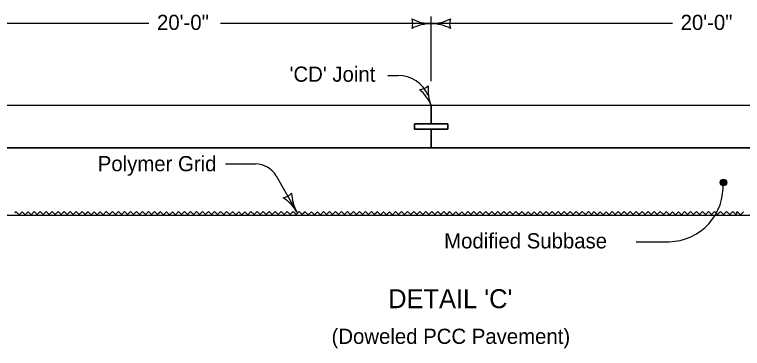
# Model space of a CAD drawing. Extents: x 5546 to 81668, y 3174 to 15999.
# Drawn here: x 14429 to 15194, y 8443 to 8795 of the extents above; entities that cross this region are included whole.
import ezdxf

# ---------------------------------------------------------------- set-up
doc = ezdxf.new("R2010")
doc.units = 0
for name, color, linetype in [('PS_BOLT', 7, 'Continuous'), ('PS_CONST', 7, 'Continuous'), ('PS_DAWA', 7, 'Continuous'), ('PS_SHAPE', 7, 'Continuous')]:
    doc.layers.add(name, color=color, linetype=linetype)

msp = doc.modelspace()

# ---------------------------------------------------------------- linework, layer by layer
at = {"layer": 'PS_BOLT'}
for p, q in [((14866.72, 8699.17), (14310.64, 8699.17)), ((15417.71, 8699.17), (14866.72, 8699.17)), ((14866.72, 8699.17), (14866.72, 8679.74)), ((14866.72, 8679.79), (14866.72, 8699.17)), ((14849.09, 8674.22), (14849.1, 8679.75)), ((14849.1, 8679.75), (14883.63, 8679.75)), ((14883.63, 8679.75), (14866.72, 8679.79)), ((14866.72, 8679.74), (14884.34, 8679.73)), ((14884.34, 8679.73), (14884.34, 8674.16)), ((14866.7, 8674.15), (14849.09, 8674.23)), ((14866.72, 8654.62), (14866.7, 8674.21)), ((14866.73, 8674.16), (14866.72, 8654.62)), ((14884.34, 8674.16), (14866.73, 8674.16)), ((14310.64, 8654.62), (14866.72, 8654.62)), ((14866.72, 8654.62), (15305.81, 8654.62))]:
    msp.add_line(p, q, dxfattribs=at)
at = {"layer": 'PS_CONST'}
for p, q in [((14821.22, 8730.75), (14831.56, 8730.75)), ((14650.52, 8637.6), (14681.92, 8637.6)), ((14703.61, 8625.03), (14725.55, 8586.74)), ((15082.31, 8555.61), (15116.87, 8555.61))]:
    msp.add_line(p, q, dxfattribs=at)
msp.add_lwpolyline([(15173.91, 8614.82), (15175.07, 8615.35), (15176.89, 8615.91), (15177.24, 8617.76), (15177, 8619.38), (15175.83, 8620.87), (15174.1, 8620.72), (15172.27, 8620.47), (15171.4, 8619.01), (15171.24, 8617.48), (15172.31, 8615.47), (15173.64, 8615.31), (15175.47, 8615.77), (15176.96, 8616.93), (15176.91, 8618.66), (15175.75, 8620.06), (15174.12, 8620.21), (15172.29, 8619.86), (15172.01, 8618.83), (15171.65, 8617.59), (15172.5, 8616.09), (15173.83, 8616.13), (15175.35, 8616.37), (15176.44, 8617.22), (15175.89, 8618.74), (15174.75, 8619.62), (15173.21, 8619.68), (15172.83, 8618.85), (15172.35, 8617.92), (15173.1, 8616.72), (15174.22, 8616.45), (15175.23, 8616.99), (15175.3, 8618.11), (15174.77, 8618.91), (15173.74, 8619.19), (15173.24, 8618.76), (15172.95, 8618.14), (15173.49, 8617.24), (15174.21, 8617.06), (15174.91, 8617.48), (15174.79, 8618.09), (15174.27, 8618.49), (15173.56, 8618.47), (15173.57, 8617.96), (15174.19, 8617.67)], dxfattribs=at)
msp.add_circle((15174.17, 8618), 3.47, dxfattribs=at)
for centre, radius, start, end in [((14831.56, 8696.1), 34.65, 22.59071, 90), ((14852.95, 8732.26), 16.51, 274.85846, 310.32516), ((14906.19, 8715.59), 42.75, 174.51932, 202.59181), ((14827.25, 8682.75), 42.75, 22.59181, 50.6643), ((14681.92, 8612.6), 25, 29.81283, 90), ((15115.81, 8613.44), 57.84, 271.04189, 4.17432), ((14707.73, 8617.84), 16.51, 282.0872, 317.5539), ((14762.64, 8608), 42.75, 181.74806, 209.82055), ((14688.47, 8565.48), 42.75, 29.82055, 57.89304)]:
    msp.add_arc(centre, radius, start, end, dxfattribs=at)
at = {"layer": 'PS_DAWA'}
for p, q in [((14866.72, 8724.76), (14866.72, 8792.66)), ((14569.76, 8785.23), (14310.64, 8785.23)), ((14866.72, 8785.23), (14645.04, 8785.23)), ((15120.33, 8785.23), (14866.72, 8785.23))]:
    msp.add_line(p, q, dxfattribs=at)
for centre, radius, start, end in [((14830.88, 8785.24), 16.51, 342.26665, 17.73335), ((14866.72, 8827.99), 42.75, 241.92751, 270), ((14866.72, 8827.99), 42.75, 270, 298.07249), ((14866.72, 8827.99), 42.75, 270, 298.07249), ((14902.56, 8785.24), 16.51, 162.26665, 197.73335), ((14902.56, 8785.24), 16.51, 162.26665, 197.73335), ((14866.72, 8742.49), 42.75, 90, 118.07249), ((14866.72, 8742.49), 42.75, 61.92751, 90), ((14866.72, 8742.49), 42.75, 61.92751, 90)]:
    msp.add_arc(centre, radius, start, end, dxfattribs=at)
at = {"layer": 'PS_SHAPE'}
for p, q in [((15417.71, 8699.17), (14310.64, 8699.17)), ((14866.72, 8699.17), (14866.72, 8679.68)), ((14884.34, 8679.73), (14849.1, 8679.75)), ((14849.1, 8679.75), (14849.1, 8674.17)), ((14884.34, 8674.16), (14884.34, 8679.73)), ((14849.1, 8674.17), (14884.34, 8674.16)), ((14866.72, 8674.17), (14866.72, 8654.62)), ((15376.64, 8654.62), (14310.64, 8654.62)), ((15398.17, 8583.34), (14310.64, 8583.34))]:
    msp.add_line(p, q, dxfattribs=at)
for points in [[(14504.59, 8585.83), (14503.01, 8584.23), (14499.83, 8587.39), (14496.68, 8584.22), (14493.49, 8587.38), (14490.33, 8584.19), (14487.17, 8587.36), (14484, 8584.18), (14480.82, 8587.34), (14477.67, 8584.16), (14474.49, 8587.33), (14471.33, 8584.15), (14468.15, 8587.31), (14465, 8584.13), (14461.81, 8587.29), (14458.65, 8584.12), (14455.49, 8587.28), (14452.32, 8584.1), (14449.15, 8587.26), (14445.99, 8584.08), (14442.81, 8587.24), (14439.65, 8584.07), (14436.48, 8587.23), (14433.32, 8584.04), (14430.14, 8587.21), (14428.72, 8586.08)], [(14580.53, 8585.83), (14578.95, 8584.23), (14575.77, 8587.39), (14572.62, 8584.22), (14569.44, 8587.38), (14566.28, 8584.19), (14563.11, 8587.36), (14559.95, 8584.18), (14556.76, 8587.34), (14553.61, 8584.16), (14550.43, 8587.33), (14547.27, 8584.15), (14544.09, 8587.31), (14540.94, 8584.13), (14537.76, 8587.29), (14534.6, 8584.12), (14531.43, 8587.28), (14528.27, 8584.1), (14525.09, 8587.26), (14521.93, 8584.08), (14518.75, 8587.24), (14515.59, 8584.07), (14512.42, 8587.23), (14509.26, 8584.04), (14506.08, 8587.21), (14504.66, 8586.08)], [(14656.39, 8585.83), (14654.82, 8584.23), (14651.63, 8587.39), (14648.48, 8584.22), (14645.3, 8587.38), (14642.14, 8584.19), (14638.97, 8587.36), (14635.81, 8584.18), (14632.63, 8587.34), (14629.47, 8584.16), (14626.29, 8587.33), (14623.13, 8584.15), (14619.95, 8587.31), (14616.8, 8584.13), (14613.62, 8587.29), (14610.46, 8584.12), (14607.29, 8587.28), (14604.13, 8584.1), (14600.95, 8587.26), (14597.79, 8584.08), (14594.61, 8587.24), (14591.46, 8584.07), (14588.28, 8587.23), (14585.12, 8584.04), (14581.95, 8587.21), (14580.52, 8586.08)], [(14732.66, 8585.83), (14731.09, 8584.23), (14727.9, 8587.39), (14724.75, 8584.22), (14721.57, 8587.38), (14718.41, 8584.19), (14715.24, 8587.36), (14712.08, 8584.18), (14708.89, 8587.34), (14705.74, 8584.16), (14702.56, 8587.33), (14699.4, 8584.15), (14696.22, 8587.31), (14693.07, 8584.13), (14689.89, 8587.29), (14686.73, 8584.12), (14683.56, 8587.28), (14680.4, 8584.1), (14677.22, 8587.26), (14674.06, 8584.08), (14670.88, 8587.24), (14667.73, 8584.07), (14664.55, 8587.23), (14661.39, 8584.04), (14658.21, 8587.21), (14656.79, 8586.08)], [(14808.79, 8585.83), (14807.21, 8584.23), (14804.03, 8587.39), (14800.87, 8584.22), (14797.69, 8587.38), (14794.53, 8584.19), (14791.36, 8587.36), (14788.2, 8584.18), (14785.02, 8587.34), (14781.87, 8584.16), (14778.68, 8587.33), (14775.52, 8584.15), (14772.35, 8587.31), (14769.19, 8584.13), (14766.01, 8587.29), (14762.85, 8584.12), (14759.68, 8587.28), (14756.52, 8584.1), (14753.35, 8587.26), (14750.19, 8584.08), (14747, 8587.24), (14743.85, 8584.07), (14740.67, 8587.23), (14737.51, 8584.04), (14734.34, 8587.21), (14732.91, 8586.08)], [(14884.73, 8585.83), (14883.15, 8584.23), (14879.97, 8587.39), (14876.82, 8584.22), (14873.63, 8587.38), (14870.47, 8584.19), (14867.3, 8587.36), (14864.14, 8584.18), (14860.96, 8587.34), (14857.81, 8584.16), (14854.62, 8587.33), (14851.46, 8584.15), (14848.29, 8587.31), (14845.14, 8584.13), (14841.95, 8587.29), (14838.79, 8584.12), (14835.62, 8587.28), (14832.46, 8584.1), (14829.29, 8587.26), (14826.13, 8584.08), (14822.94, 8587.24), (14819.79, 8584.07), (14816.62, 8587.23), (14813.46, 8584.04), (14810.28, 8587.21), (14808.85, 8586.08)], [(14960.59, 8585.83), (14959.01, 8584.23), (14955.83, 8587.39), (14952.68, 8584.22), (14949.49, 8587.38), (14946.33, 8584.19), (14943.17, 8587.36), (14940.01, 8584.18), (14936.82, 8587.34), (14933.67, 8584.16), (14930.49, 8587.33), (14927.33, 8584.15), (14924.15, 8587.31), (14921, 8584.13), (14917.81, 8587.29), (14914.65, 8584.12), (14911.49, 8587.28), (14908.33, 8584.1), (14905.15, 8587.26), (14901.99, 8584.08), (14898.81, 8587.24), (14895.65, 8584.07), (14892.48, 8587.23), (14889.32, 8584.04), (14886.14, 8587.21), (14884.72, 8586.08)], [(15036.72, 8585.83), (15035.14, 8584.23), (15031.96, 8587.39), (15028.8, 8584.22), (15025.62, 8587.38), (15022.46, 8584.19), (15019.29, 8587.36), (15016.13, 8584.18), (15012.95, 8587.34), (15009.79, 8584.16), (15006.61, 8587.33), (15003.45, 8584.15), (15000.28, 8587.31), (14997.12, 8584.13), (14993.94, 8587.29), (14990.78, 8584.12), (14987.61, 8587.28), (14984.45, 8584.1), (14981.28, 8587.26), (14978.11, 8584.08), (14974.93, 8587.24), (14971.78, 8584.07), (14968.6, 8587.23), (14965.44, 8584.04), (14962.27, 8587.21), (14960.84, 8586.08)], [(15112.4, 8585.83), (15110.82, 8584.23), (15107.64, 8587.39), (15104.49, 8584.22), (15101.31, 8587.38), (15098.15, 8584.19), (15094.98, 8587.36), (15091.82, 8584.18), (15088.63, 8587.34), (15085.48, 8584.16), (15082.3, 8587.33), (15079.14, 8584.15), (15075.96, 8587.31), (15072.81, 8584.13), (15069.63, 8587.29), (15066.47, 8584.12), (15063.3, 8587.28), (15060.14, 8584.1), (15056.96, 8587.26), (15053.8, 8584.08), (15050.62, 8587.24), (15047.46, 8584.07), (15044.29, 8587.23), (15041.13, 8584.04), (15037.95, 8587.21), (15036.53, 8586.08)], [(15188.49, 8585.83), (15186.91, 8584.23), (15183.73, 8587.39), (15180.57, 8584.22), (15177.39, 8587.38), (15174.23, 8584.19), (15171.06, 8587.36), (15167.9, 8584.18), (15164.72, 8587.34), (15161.57, 8584.16), (15158.38, 8587.33), (15155.22, 8584.15), (15152.05, 8587.31), (15148.89, 8584.13), (15145.71, 8587.29), (15142.55, 8584.12), (15139.38, 8587.28), (15136.22, 8584.1), (15133.05, 8587.26), (15129.89, 8584.08), (15126.7, 8587.24), (15123.55, 8584.07), (15120.37, 8587.23), (15117.21, 8584.04), (15114.04, 8587.21), (15112.61, 8586.08)], [(15195.27, 8587.23), (15192.1, 8584.04), (15188.93, 8587.21), (15187.5, 8586.08)]]:
    msp.add_lwpolyline(points, dxfattribs=at)

# ---------------------------------------------------------------- texts
at = {"layer": 'PS_BOLT'}
msp.add_text("DETAIL 'C'", height=20, dxfattribs=at).set_placement((14821.47, 8485.6))
at = {"layer": 'PS_CONST'}
for s, p in [("'CD' Joint", (14717.79, 8724.08)), ('Polymer Grid', (14516.07, 8629.81)), ('Modified Subbase', (14880.33, 8548.54))]:
    msp.add_text(s, height=16, dxfattribs=at).set_placement(p)
at = {"layer": 'PS_DAWA'}
for p in [(14578.4, 8778.6), (15128.98, 8778.6)]:
    msp.add_text('20\'-0"', height=16, dxfattribs=at).set_placement(p)
at = {"layer": 'PS_SHAPE'}
msp.add_text('(Doweled PCC Pavement)', height=16, dxfattribs=at).set_placement((14761.94, 8448))

doc.saveas('drawing.dxf')
